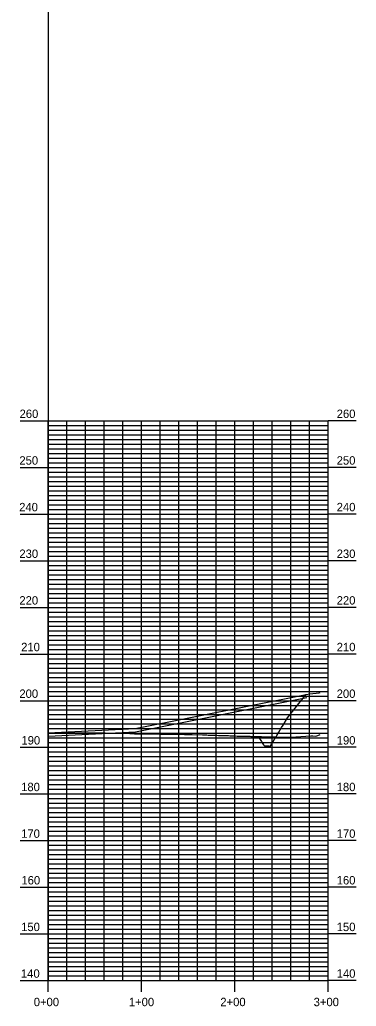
# Model space of a CAD drawing. Extents: x 1451449 to 1456010, y 297581 to 299758.
# Drawn here: x 1451449 to 1451810, y 297581 to 298638 of the extents above; entities that cross this region are included whole.
import ezdxf

# ---------------------------------------------------------------- set-up
doc = ezdxf.new("R2010")
doc.units = 0
for name, color, linetype in [('51', 7, 'Continuous'), ('Grid', 7, 'Continuous'), ('Grid_Labels', 7, 'Continuous'), ('Grid_Major', 7, 'Continuous'), ('Grid_Minor', 7, 'Continuous'), ('PR_exist_ground', 7, 'Continuous'), ('PRF_Bridge', 7, 'Continuous'), ('R_Fin Surface', 7, 'Continuous')]:
    doc.layers.add(name, color=color, linetype=linetype)

msp = doc.modelspace()

# ---------------------------------------------------------------- linework, layer by layer
at = {"layer": 'Grid'}
for p, q in [((1451449.7, 298208.5), (1451479.7, 298208.5)), ((1451449.7, 298208.5), (1451479.7, 298208.5)), ((1451479.7, 297608.5), (1451479.7, 298208.5)), ((1451779.7, 297608.5), (1451779.7, 298208.5)), ((1451809.7, 298208.5), (1451779.7, 298208.5)), ((1451809.7, 298208.5), (1451779.7, 298208.5)), ((1451479.7, 298203.5), (1451482.7, 298203.5)), ((1451479.7, 298198.5), (1451482.7, 298198.5)), ((1451479.7, 298193.5), (1451482.7, 298193.5)), ((1451479.7, 298188.5), (1451482.7, 298188.5)), ((1451479.7, 298183.5), (1451482.7, 298183.5)), ((1451479.7, 298178.5), (1451482.7, 298178.5)), ((1451479.7, 298173.5), (1451482.7, 298173.5)), ((1451479.7, 298168.5), (1451482.7, 298168.5)), ((1451479.7, 298163.5), (1451482.7, 298163.5)), ((1451449.7, 298158.5), (1451479.7, 298158.5)), ((1451479.7, 298153.5), (1451482.7, 298153.5)), ((1451809.7, 298158.5), (1451779.7, 298158.5)), ((1451479.7, 298148.5), (1451482.7, 298148.5)), ((1451479.7, 298143.5), (1451482.7, 298143.5)), ((1451479.7, 298138.5), (1451482.7, 298138.5)), ((1451479.7, 298133.5), (1451482.7, 298133.5)), ((1451479.7, 298128.5), (1451482.7, 298128.5)), ((1451479.7, 298123.5), (1451482.7, 298123.5)), ((1451479.7, 298118.5), (1451482.7, 298118.5)), ((1451479.7, 298113.5), (1451482.7, 298113.5)), ((1451449.7, 298108.5), (1451479.7, 298108.5)), ((1451479.7, 298103.5), (1451482.7, 298103.5)), ((1451809.7, 298108.5), (1451779.7, 298108.5)), ((1451479.7, 298098.5), (1451482.7, 298098.5)), ((1451479.7, 298093.5), (1451482.7, 298093.5)), ((1451479.7, 298088.5), (1451482.7, 298088.5)), ((1451479.7, 298083.5), (1451482.7, 298083.5)), ((1451479.7, 298078.5), (1451482.7, 298078.5)), ((1451479.7, 298073.5), (1451482.7, 298073.5)), ((1451479.7, 298068.5), (1451482.7, 298068.5)), ((1451449.7, 298058.5), (1451479.7, 298058.5)), ((1451479.7, 298063.5), (1451482.7, 298063.5)), ((1451809.7, 298058.5), (1451779.7, 298058.5)), ((1451479.7, 298053.5), (1451482.7, 298053.5)), ((1451479.7, 298048.5), (1451482.7, 298048.5)), ((1451479.7, 298043.5), (1451482.7, 298043.5)), ((1451479.7, 298038.5), (1451482.7, 298038.5)), ((1451479.7, 298033.5), (1451482.7, 298033.5)), ((1451479.7, 298028.5), (1451482.7, 298028.5)), ((1451479.7, 298023.5), (1451482.7, 298023.5)), ((1451479.7, 298018.5), (1451482.7, 298018.5)), ((1451449.7, 298008.5), (1451479.7, 298008.5)), ((1451479.7, 298013.5), (1451482.7, 298013.5)), ((1451479.7, 298003.5), (1451482.7, 298003.5)), ((1451809.7, 298008.5), (1451779.7, 298008.5)), ((1451479.7, 297998.5), (1451482.7, 297998.5)), ((1451479.7, 297993.5), (1451482.7, 297993.5)), ((1451479.7, 297988.5), (1451482.7, 297988.5)), ((1451479.7, 297983.5), (1451482.7, 297983.5)), ((1451479.7, 297978.5), (1451482.7, 297978.5)), ((1451479.7, 297973.5), (1451482.7, 297973.5)), ((1451479.7, 297968.5), (1451482.7, 297968.5)), ((1451479.7, 297963.5), (1451482.7, 297963.5)), ((1451449.7, 297958.5), (1451479.7, 297958.5)), ((1451479.7, 297953.5), (1451482.7, 297953.5)), ((1451809.7, 297958.5), (1451779.7, 297958.5)), ((1451479.7, 297948.5), (1451482.7, 297948.5)), ((1451479.7, 297943.5), (1451482.7, 297943.5)), ((1451479.7, 297938.5), (1451482.7, 297938.5)), ((1451479.7, 297933.5), (1451482.7, 297933.5)), ((1451479.7, 297928.5), (1451482.7, 297928.5)), ((1451479.7, 297923.5), (1451482.7, 297923.5)), ((1451449.7, 297908.5), (1451479.7, 297908.5)), ((1451479.7, 297918.5), (1451482.7, 297918.5)), ((1451479.7, 297913.5), (1451482.7, 297913.5)), ((1451809.7, 297908.5), (1451779.7, 297908.5)), ((1451479.7, 297903.5), (1451482.7, 297903.5)), ((1451479.7, 297898.5), (1451482.7, 297898.5)), ((1451479.7, 297893.5), (1451482.7, 297893.5)), ((1451479.7, 297888.5), (1451482.7, 297888.5)), ((1451479.7, 297883.5), (1451482.7, 297883.5)), ((1451479.7, 297878.5), (1451482.7, 297878.5)), ((1451479.7, 297873.5), (1451482.7, 297873.5)), ((1451479.7, 297868.5), (1451482.7, 297868.5)), ((1451449.7, 297858.5), (1451479.7, 297858.5)), ((1451479.7, 297863.5), (1451482.7, 297863.5)), ((1451809.7, 297858.5), (1451779.7, 297858.5)), ((1451479.7, 297853.5), (1451482.7, 297853.5)), ((1451479.7, 297848.5), (1451482.7, 297848.5)), ((1451479.7, 297843.5), (1451482.7, 297843.5)), ((1451479.7, 297838.5), (1451482.7, 297838.5)), ((1451479.7, 297833.5), (1451482.7, 297833.5)), ((1451479.7, 297828.5), (1451482.7, 297828.5)), ((1451479.7, 297823.5), (1451482.7, 297823.5)), ((1451479.7, 297818.5), (1451482.7, 297818.5)), ((1451479.7, 297813.5), (1451482.7, 297813.5)), ((1451449.7, 297808.5), (1451479.7, 297808.5)), ((1451479.7, 297803.5), (1451482.7, 297803.5)), ((1451809.7, 297808.5), (1451779.7, 297808.5)), ((1451479.7, 297798.5), (1451482.7, 297798.5)), ((1451479.7, 297793.5), (1451482.7, 297793.5)), ((1451479.7, 297788.5), (1451482.7, 297788.5)), ((1451479.7, 297783.5), (1451482.7, 297783.5)), ((1451479.7, 297778.5), (1451482.7, 297778.5)), ((1451479.7, 297773.5), (1451482.7, 297773.5)), ((1451479.7, 297768.5), (1451482.7, 297768.5)), ((1451479.7, 297763.5), (1451482.7, 297763.5)), ((1451449.7, 297758.5), (1451479.7, 297758.5)), ((1451479.7, 297753.5), (1451482.7, 297753.5)), ((1451809.7, 297758.5), (1451779.7, 297758.5)), ((1451479.7, 297748.5), (1451482.7, 297748.5)), ((1451479.7, 297743.5), (1451482.7, 297743.5)), ((1451479.7, 297738.5), (1451482.7, 297738.5)), ((1451479.7, 297733.5), (1451482.7, 297733.5)), ((1451479.7, 297728.5), (1451482.7, 297728.5)), ((1451479.7, 297723.5), (1451482.7, 297723.5)), ((1451479.7, 297718.5), (1451482.7, 297718.5)), ((1451449.7, 297708.5), (1451479.7, 297708.5)), ((1451479.7, 297713.5), (1451482.7, 297713.5)), ((1451809.7, 297708.5), (1451779.7, 297708.5)), ((1451479.7, 297703.5), (1451482.7, 297703.5)), ((1451479.7, 297698.5), (1451482.7, 297698.5)), ((1451479.7, 297693.5), (1451482.7, 297693.5)), ((1451479.7, 297688.5), (1451482.7, 297688.5)), ((1451479.7, 297683.5), (1451482.7, 297683.5)), ((1451479.7, 297678.5), (1451482.7, 297678.5)), ((1451479.7, 297673.5), (1451482.7, 297673.5)), ((1451479.7, 297668.5), (1451482.7, 297668.5)), ((1451449.7, 297658.5), (1451479.7, 297658.5)), ((1451479.7, 297663.5), (1451482.7, 297663.5)), ((1451809.7, 297658.5), (1451779.7, 297658.5)), ((1451479.7, 297653.5), (1451482.7, 297653.5)), ((1451479.7, 297648.5), (1451482.7, 297648.5)), ((1451479.7, 297643.5), (1451482.7, 297643.5)), ((1451479.7, 297638.5), (1451482.7, 297638.5)), ((1451479.7, 297633.5), (1451482.7, 297633.5)), ((1451479.7, 297628.5), (1451482.7, 297628.5)), ((1451479.7, 297623.5), (1451482.7, 297623.5)), ((1451479.7, 297618.5), (1451482.7, 297618.5)), ((1451479.7, 297613.5), (1451482.7, 297613.5)), ((1451449.7, 297608.5), (1451479.7, 297608.5)), ((1451479.7, 297608.5), (1451779.7, 297608.5)), ((1451479.7, 297596.5), (1451479.7, 297608.5)), ((1451579.7, 297596.5), (1451579.7, 297608.5)), ((1451679.7, 297596.5), (1451679.7, 297608.5)), ((1451809.7, 297608.5), (1451779.7, 297608.5)), ((1451779.7, 297596.5), (1451779.7, 297608.5))]:
    msp.add_line(p, q, dxfattribs=at)
at = {"layer": 'Grid_Major'}
for p, q in [((1451479.7, 298208.5), (1451779.7, 298208.5)), ((1451479.7, 298208.5), (1451779.7, 298208.5)), ((1451579.7, 297608.5), (1451579.7, 298208.5)), ((1451679.7, 297608.5), (1451679.7, 298208.5)), ((1451479.7, 298158.5), (1451779.7, 298158.5)), ((1451479.7, 298108.5), (1451779.7, 298108.5)), ((1451479.7, 298058.5), (1451779.7, 298058.5)), ((1451479.7, 298008.5), (1451779.7, 298008.5)), ((1451479.7, 297958.5), (1451779.7, 297958.5)), ((1451479.7, 297908.5), (1451779.7, 297908.5)), ((1451479.7, 297858.5), (1451779.7, 297858.5)), ((1451479.7, 297808.5), (1451779.7, 297808.5)), ((1451479.7, 297758.5), (1451779.7, 297758.5)), ((1451479.7, 297708.5), (1451779.7, 297708.5)), ((1451479.7, 297658.5), (1451779.7, 297658.5))]:
    msp.add_line(p, q, dxfattribs=at)
at = {"layer": 'Grid_Minor'}
for p, q in [((1451499.7, 297608.5), (1451499.7, 298208.5)), ((1451519.7, 297608.5), (1451519.7, 298208.5)), ((1451539.7, 297608.5), (1451539.7, 298208.5)), ((1451559.7, 297608.5), (1451559.7, 298208.5)), ((1451599.7, 297608.5), (1451599.7, 298208.5)), ((1451619.7, 297608.5), (1451619.7, 298208.5)), ((1451639.7, 297608.5), (1451639.7, 298208.5)), ((1451659.7, 297608.5), (1451659.7, 298208.5)), ((1451699.7, 297608.5), (1451699.7, 298208.5)), ((1451719.7, 297608.5), (1451719.7, 298208.5)), ((1451739.7, 297608.5), (1451739.7, 298208.5)), ((1451759.7, 297608.5), (1451759.7, 298208.5)), ((1451479.7, 298203.5), (1451779.7, 298203.5)), ((1451479.7, 298198.5), (1451779.7, 298198.5)), ((1451479.7, 298193.5), (1451779.7, 298193.5)), ((1451479.7, 298188.5), (1451779.7, 298188.5)), ((1451479.7, 298183.5), (1451779.7, 298183.5)), ((1451479.7, 298178.5), (1451779.7, 298178.5)), ((1451479.7, 298173.5), (1451779.7, 298173.5)), ((1451479.7, 298168.5), (1451779.7, 298168.5)), ((1451479.7, 298163.5), (1451779.7, 298163.5)), ((1451479.7, 298153.5), (1451779.7, 298153.5)), ((1451479.7, 298148.5), (1451779.7, 298148.5)), ((1451479.7, 298143.5), (1451779.7, 298143.5)), ((1451479.7, 298138.5), (1451779.7, 298138.5)), ((1451479.7, 298133.5), (1451779.7, 298133.5)), ((1451479.7, 298128.5), (1451779.7, 298128.5)), ((1451479.7, 298123.5), (1451779.7, 298123.5)), ((1451479.7, 298118.5), (1451779.7, 298118.5)), ((1451479.7, 298113.5), (1451779.7, 298113.5)), ((1451479.7, 298103.5), (1451779.7, 298103.5)), ((1451479.7, 298098.5), (1451779.7, 298098.5)), ((1451479.7, 298093.5), (1451779.7, 298093.5)), ((1451479.7, 298088.5), (1451779.7, 298088.5)), ((1451479.7, 298083.5), (1451779.7, 298083.5)), ((1451479.7, 298078.5), (1451779.7, 298078.5)), ((1451479.7, 298073.5), (1451779.7, 298073.5)), ((1451479.7, 298068.5), (1451779.7, 298068.5)), ((1451479.7, 298063.5), (1451779.7, 298063.5)), ((1451479.7, 298053.5), (1451779.7, 298053.5)), ((1451479.7, 298048.5), (1451779.7, 298048.5)), ((1451479.7, 298043.5), (1451779.7, 298043.5)), ((1451479.7, 298038.5), (1451779.7, 298038.5)), ((1451479.7, 298033.5), (1451779.7, 298033.5)), ((1451479.7, 298028.5), (1451779.7, 298028.5)), ((1451479.7, 298023.5), (1451779.7, 298023.5)), ((1451479.7, 298018.5), (1451779.7, 298018.5)), ((1451479.7, 298013.5), (1451779.7, 298013.5)), ((1451479.7, 298003.5), (1451779.7, 298003.5)), ((1451479.7, 297998.5), (1451779.7, 297998.5)), ((1451479.7, 297993.5), (1451779.7, 297993.5)), ((1451479.7, 297988.5), (1451779.7, 297988.5)), ((1451479.7, 297983.5), (1451779.7, 297983.5)), ((1451479.7, 297978.5), (1451779.7, 297978.5)), ((1451479.7, 297973.5), (1451779.7, 297973.5)), ((1451479.7, 297968.5), (1451779.7, 297968.5)), ((1451479.7, 297963.5), (1451779.7, 297963.5)), ((1451479.7, 297953.5), (1451779.7, 297953.5)), ((1451479.7, 297948.5), (1451779.7, 297948.5)), ((1451479.7, 297943.5), (1451779.7, 297943.5)), ((1451479.7, 297938.5), (1451779.7, 297938.5)), ((1451479.7, 297933.5), (1451779.7, 297933.5)), ((1451479.7, 297928.5), (1451779.7, 297928.5)), ((1451479.7, 297923.5), (1451779.7, 297923.5)), ((1451479.7, 297918.5), (1451779.7, 297918.5)), ((1451479.7, 297913.5), (1451779.7, 297913.5)), ((1451479.7, 297903.5), (1451779.7, 297903.5)), ((1451479.7, 297898.5), (1451779.7, 297898.5)), ((1451479.7, 297893.5), (1451779.7, 297893.5)), ((1451479.7, 297888.5), (1451779.7, 297888.5)), ((1451479.7, 297883.5), (1451779.7, 297883.5)), ((1451479.7, 297878.5), (1451779.7, 297878.5)), ((1451479.7, 297873.5), (1451779.7, 297873.5)), ((1451479.7, 297868.5), (1451779.7, 297868.5)), ((1451479.7, 297863.5), (1451779.7, 297863.5)), ((1451479.7, 297853.5), (1451779.7, 297853.5)), ((1451479.7, 297848.5), (1451779.7, 297848.5)), ((1451479.7, 297843.5), (1451779.7, 297843.5)), ((1451479.7, 297838.5), (1451779.7, 297838.5)), ((1451479.7, 297833.5), (1451779.7, 297833.5)), ((1451479.7, 297828.5), (1451779.7, 297828.5)), ((1451479.7, 297823.5), (1451779.7, 297823.5)), ((1451479.7, 297818.5), (1451779.7, 297818.5)), ((1451479.7, 297813.5), (1451779.7, 297813.5)), ((1451479.7, 297803.5), (1451779.7, 297803.5)), ((1451479.7, 297798.5), (1451779.7, 297798.5)), ((1451479.7, 297793.5), (1451779.7, 297793.5)), ((1451479.7, 297788.5), (1451779.7, 297788.5)), ((1451479.7, 297783.5), (1451779.7, 297783.5)), ((1451479.7, 297778.5), (1451779.7, 297778.5)), ((1451479.7, 297773.5), (1451779.7, 297773.5)), ((1451479.7, 297768.5), (1451779.7, 297768.5)), ((1451479.7, 297763.5), (1451779.7, 297763.5)), ((1451479.7, 297753.5), (1451779.7, 297753.5)), ((1451479.7, 297748.5), (1451779.7, 297748.5)), ((1451479.7, 297743.5), (1451779.7, 297743.5)), ((1451479.7, 297738.5), (1451779.7, 297738.5)), ((1451479.7, 297733.5), (1451779.7, 297733.5)), ((1451479.7, 297728.5), (1451779.7, 297728.5)), ((1451479.7, 297723.5), (1451779.7, 297723.5)), ((1451479.7, 297718.5), (1451779.7, 297718.5)), ((1451479.7, 297713.5), (1451779.7, 297713.5)), ((1451479.7, 297703.5), (1451779.7, 297703.5)), ((1451479.7, 297698.5), (1451779.7, 297698.5)), ((1451479.7, 297693.5), (1451779.7, 297693.5)), ((1451479.7, 297688.5), (1451779.7, 297688.5)), ((1451479.7, 297683.5), (1451779.7, 297683.5)), ((1451479.7, 297678.5), (1451779.7, 297678.5)), ((1451479.7, 297673.5), (1451779.7, 297673.5)), ((1451479.7, 297668.5), (1451779.7, 297668.5)), ((1451479.7, 297663.5), (1451779.7, 297663.5)), ((1451479.7, 297653.5), (1451779.7, 297653.5)), ((1451479.7, 297648.5), (1451779.7, 297648.5)), ((1451479.7, 297643.5), (1451779.7, 297643.5)), ((1451479.7, 297638.5), (1451779.7, 297638.5)), ((1451479.7, 297633.5), (1451779.7, 297633.5)), ((1451479.7, 297628.5), (1451779.7, 297628.5)), ((1451479.7, 297623.5), (1451779.7, 297623.5)), ((1451479.7, 297618.5), (1451779.7, 297618.5)), ((1451479.7, 297613.5), (1451779.7, 297613.5))]:
    msp.add_line(p, q, dxfattribs=at)
at = {"layer": 'PR_exist_ground'}
for p, q in [((1451572.7, 297878.5), (1451756, 297915.2)), ((1451572.7, 297878.5), (1451756, 297915.2)), ((1451573.2, 297875.2), (1451756.6, 297911.9)), ((1451479.7, 297873.9), (1451572.7, 297878.5)), ((1451479.7, 297873.9), (1451572.7, 297878.5)), ((1451479.7, 297873.9), (1451572.7, 297878.5)), ((1451479.8, 297870.6), (1451573.2, 297875.2))]:
    msp.add_line(p, q, dxfattribs=at)
msp.add_lwpolyline([(1451479.7, 297873.9), (1451485.6, 297873.9), (1451486.7, 297874), (1451488, 297874), (1451489.3, 297874), (1451490.6, 297874), (1451491.9, 297874.1), (1451493.2, 297874.1), (1451494.6, 297874.1), (1451495, 297874.1), (1451495.9, 297874.1), (1451497.2, 297874.1), (1451498.5, 297874.2), (1451499.8, 297874.2), (1451499.9, 297874.2), (1451501.1, 297874.2), (1451502.5, 297874.2), (1451503.5, 297874.2), (1451503.8, 297874.2), (1451505.1, 297874.1), (1451505.1, 297874.1), (1451506.4, 297874.1), (1451507.6, 297874), (1451507.7, 297874), (1451509.1, 297874), (1451510.4, 297874), (1451511.7, 297874), (1451513, 297874), (1451513.2, 297874), (1451513.2, 297874), (1451514.3, 297874.1), (1451515.6, 297874.1), (1451517, 297874.1), (1451518.3, 297874.1), (1451519.6, 297874.1), (1451520.9, 297874.1), (1451521.2, 297874.1), (1451522.2, 297874.1), (1451523.5, 297874.1), (1451524.9, 297874.1), (1451526.2, 297874.1), (1451527.5, 297874.1), (1451528.8, 297874.1), (1451530.1, 297874.1), (1451531.4, 297874.1), (1451531.7, 297874.1), (1451532.8, 297874), (1451534.1, 297874), (1451535.4, 297874), (1451536.7, 297874), (1451538, 297873.9), (1451539.3, 297873.9), (1451540.7, 297873.9), (1451542, 297873.8), (1451543.3, 297873.8), (1451544.4, 297873.8), (1451544.6, 297873.8), (1451549.9, 297873.7), (1451567, 297873.2), (1451568, 297873.2), (1451572, 297873.1), (1451583.1, 297872.9), (1451585.1, 297872.8), (1451595.7, 297872.8), (1451598.8, 297872.7), (1451608.4, 297872.7), (1451612.3, 297872.6), (1451621.1, 297872.5), (1451625.8, 297872.3), (1451633.8, 297872.3), (1451644.9, 297871.9), (1451646.5, 297871.9), (1451648.1, 297871.8), (1451649.6, 297871.8), (1451651.1, 297871.7), (1451652.5, 297871.7), (1451652.7, 297871.7), (1451654.2, 297871.6), (1451655.8, 297871.6), (1451657.3, 297871.5), (1451658.8, 297871.4), (1451660.4, 297871.4), (1451661.9, 297871.3), (1451662.8, 297871.3), (1451663.5, 297871.3), (1451665, 297871.2), (1451666.5, 297871.2), (1451668.1, 297871.1), (1451669.6, 297871.1), (1451671.2, 297871), (1451672.2, 297871), (1451672.7, 297871), (1451674.3, 297870.9), (1451675.8, 297870.9), (1451677.3, 297870.8), (1451678.9, 297870.7), (1451680.2, 297870.7), (1451680.4, 297870.7), (1451682, 297870.6), (1451683.5, 297870.6), (1451685, 297870.6), (1451686.6, 297870.5), (1451688.1, 297870.5), (1451689.7, 297870.4), (1451691.2, 297870.4), (1451692.7, 297870.4), (1451694.3, 297870.3), (1451695.8, 297870.3), (1451696.8, 297870.2), (1451697.4, 297870.2), (1451698.9, 297870.2), (1451700.5, 297870.2), (1451701.4, 297870.1), (1451702, 297870.1), (1451703.5, 297870.1), (1451705.1, 297870), (1451706.6, 297870), (1451708.2, 297870), (1451709.7, 297869.9), (1451711.2, 297869.9), (1451712.8, 297869.9), (1451714.3, 297869.9), (1451715.9, 297869.8), (1451717.4, 297869.8), (1451718.5, 297869.8), (1451718.9, 297869.8), (1451720.5, 297869.7), (1451722, 297869.6), (1451723.6, 297869.6), (1451725.1, 297869.5), (1451726.7, 297869.5), (1451728.2, 297869.4), (1451729.7, 297869.4), (1451731.3, 297869.3), (1451732.6, 297869.3), (1451744.8, 297869.7), (1451761.1, 297870.8), (1451763.2, 297870.7), (1451766.2, 297870.4), (1451768.4, 297871.3), (1451770.9, 297872.2)], dxfattribs=at)
at = {"layer": 'PRF_Bridge'}
msp.add_line((1451479.7, 298953.5), (1451479.7, 297608.5), dxfattribs=at)
at = {"layer": 'R_Fin Surface'}
msp.add_lwpolyline([(1451704.6, 297870.1), (1451705.1, 297869.3), (1451705.4, 297868.8), (1451705.9, 297868.1), (1451706.6, 297867), (1451708, 297864.9), (1451708.2, 297864.7), (1451709.7, 297862.3), (1451710.4, 297861.3), (1451710.4, 297861.2), (1451710.7, 297860.7), (1451710.9, 297860.4), (1451711.2, 297860), (1451711.2, 297860), (1451712.8, 297860), (1451713.7, 297860), (1451714.3, 297860), (1451715.9, 297860), (1451715.9, 297860), (1451716.8, 297859.9), (1451717.4, 297859.9), (1451717.6, 297859.9), (1451718.9, 297862.1), (1451720.3, 297864.3), (1451720.5, 297864.6), (1451722, 297867.1), (1451723.6, 297869.6), (1451723.7, 297869.9), (1451724.5, 297871.2), (1451725.1, 297872.2), (1451725.4, 297872.7), (1451726.7, 297874.7), (1451728.1, 297877.1), (1451728.2, 297877.3), (1451729.7, 297879.8), (1451731.3, 297882.4), (1451736, 297890.2), (1451751, 297909), (1451751.6, 297909.7), (1451755.8, 297915), (1451756, 297915.2), (1451759.9, 297916), (1451760, 297916), (1451769.8, 297917), (1451770.9, 297917.1)], dxfattribs=at)

# ---------------------------------------------------------------- texts
at = {"layer": '51'}
msp.add_text('-', height=0.0001, dxfattribs=at).set_placement((1451479.7, 297608.5))
at = {"layer": 'Grid_Labels'}
for s, p in [('260', (1451448.9, 298211.5)), ('260', (1451448.9, 298211.5)), ('260', (1451788.7, 298211.5)), ('260', (1451788.7, 298211.5)), ('250', (1451448.7, 298161.5)), ('250', (1451788.7, 298161.5)), ('240', (1451448.5, 298111.5)), ('240', (1451788.7, 298111.5)), ('230', (1451448.7, 298061.5)), ('230', (1451788.7, 298061.5)), ('220', (1451448.7, 298011.5)), ('220', (1451788.7, 298011.5)), ('210', (1451450.6, 297961.5)), ('210', (1451788.7, 297961.5)), ('200', (1451448.7, 297911.5)), ('200', (1451788.7, 297911.5)), ('190', (1451450.9, 297861.5)), ('190', (1451788.7, 297861.5)), ('180', (1451450.6, 297811.5)), ('180', (1451788.7, 297811.5)), ('170', (1451450.6, 297761.5)), ('170', (1451788.7, 297761.5)), ('160', (1451450.9, 297711.5)), ('160', (1451788.7, 297711.5)), ('150', (1451450.6, 297661.5)), ('150', (1451788.7, 297661.5)), ('140', (1451450.4, 297611.5)), ('140', (1451788.7, 297611.5)), ('0+00', (1451464.1, 297581)), ('1+00', (1451566, 297581)), ('2+00', (1451664, 297581)), ('3+00', (1451764, 297581))]:
    msp.add_text(s, height=9, dxfattribs=at).set_placement(p)

doc.saveas('drawing.dxf')
